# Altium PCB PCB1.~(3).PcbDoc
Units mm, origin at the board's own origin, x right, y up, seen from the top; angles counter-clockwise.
Board outline 70 x 70 mm, 4 copper layers (Top Layer, Internal Plane 1, Internal Plane 2, Bottom Layer), stack 0.462 mm thick; 10 components, 13 nets, 53 pads, 0 vias.
Unrouted connection lines stored in the file: 9.
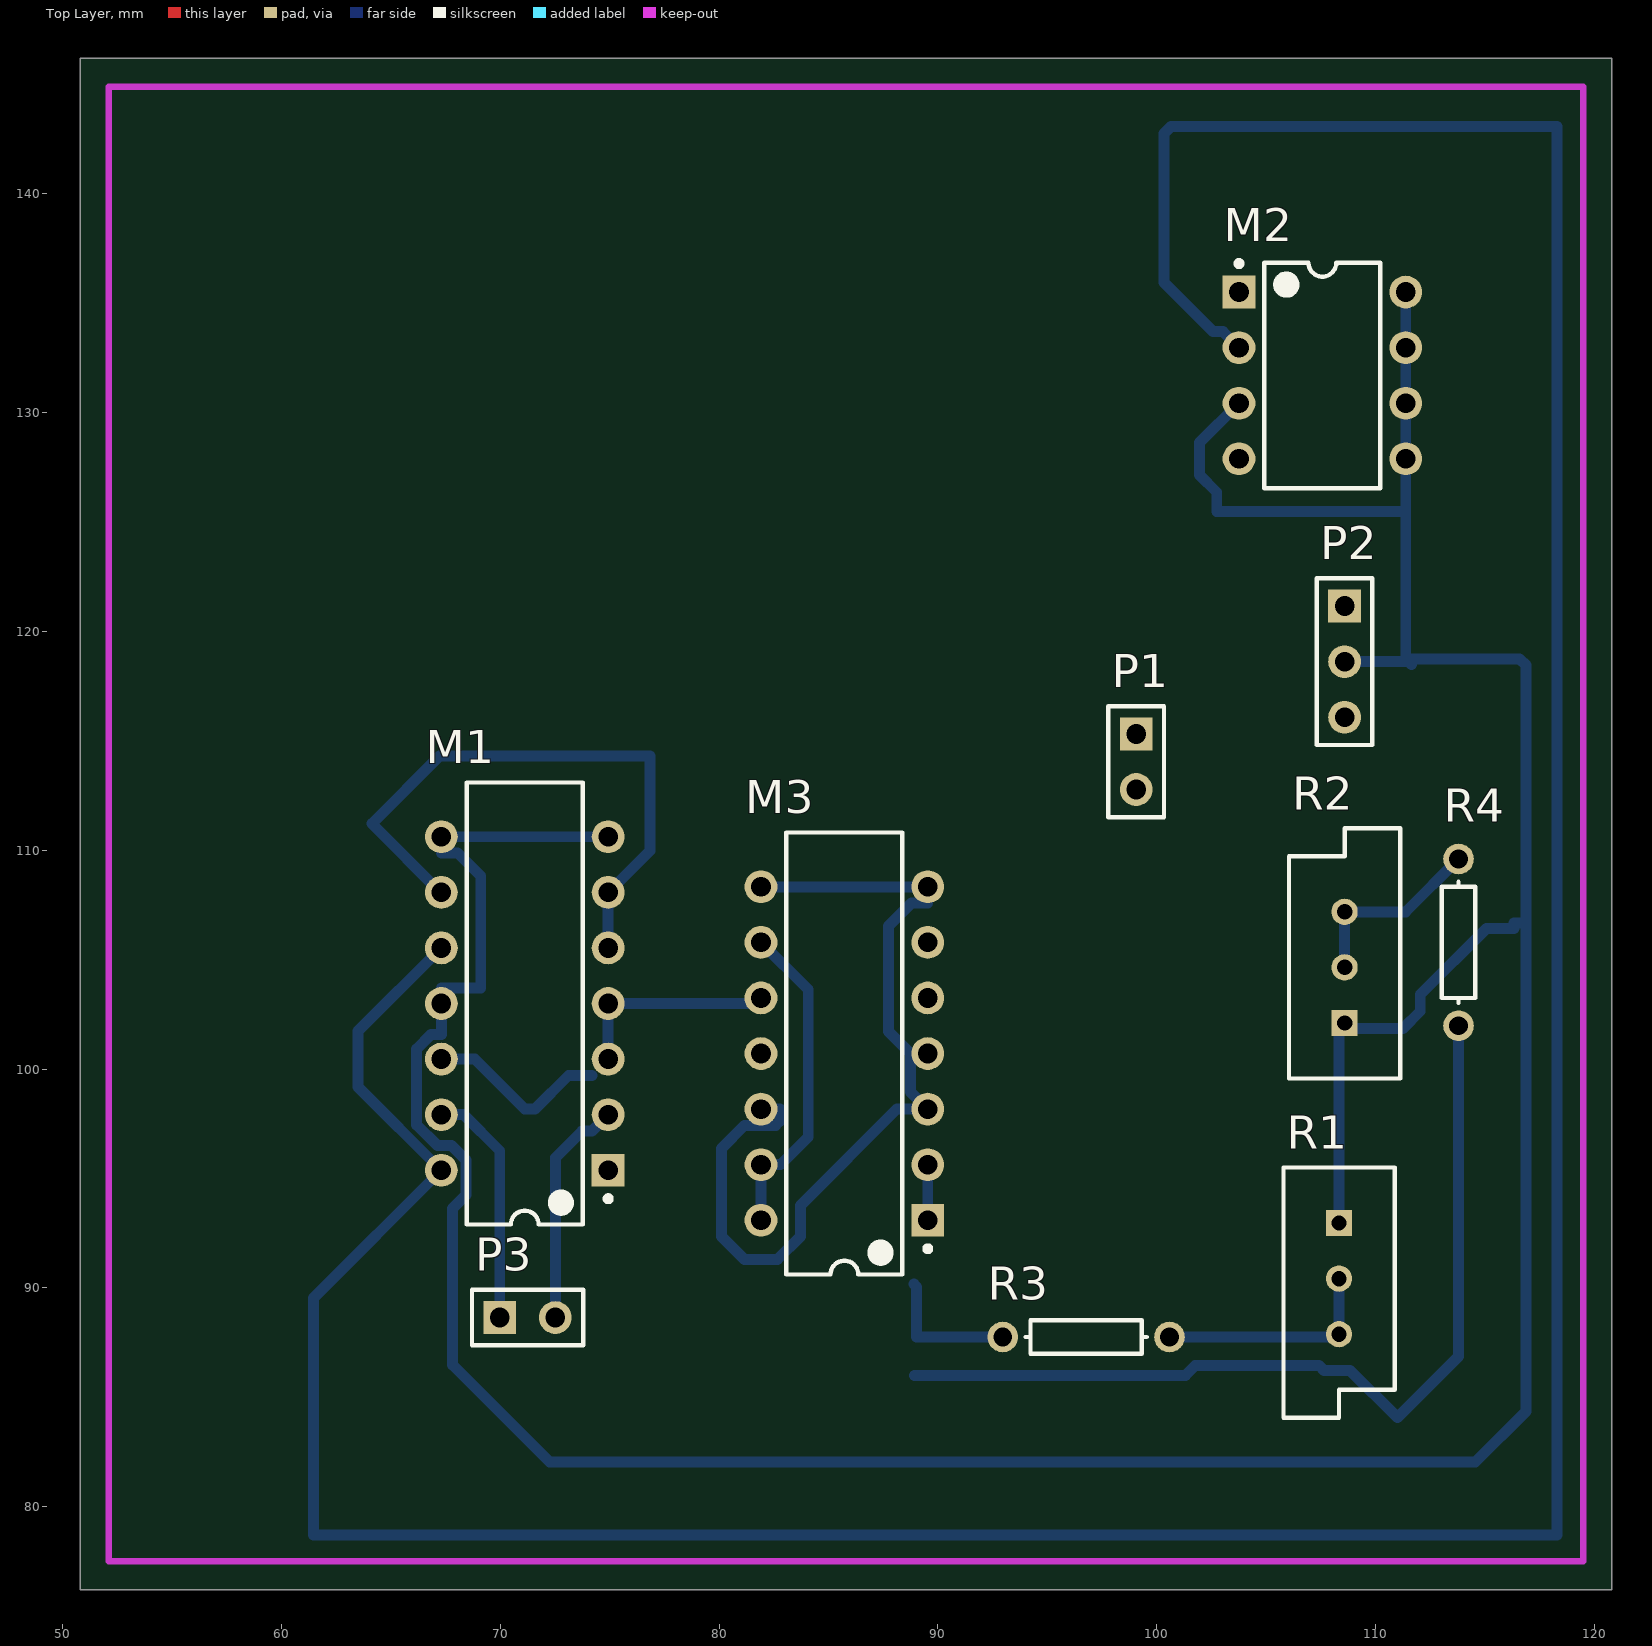
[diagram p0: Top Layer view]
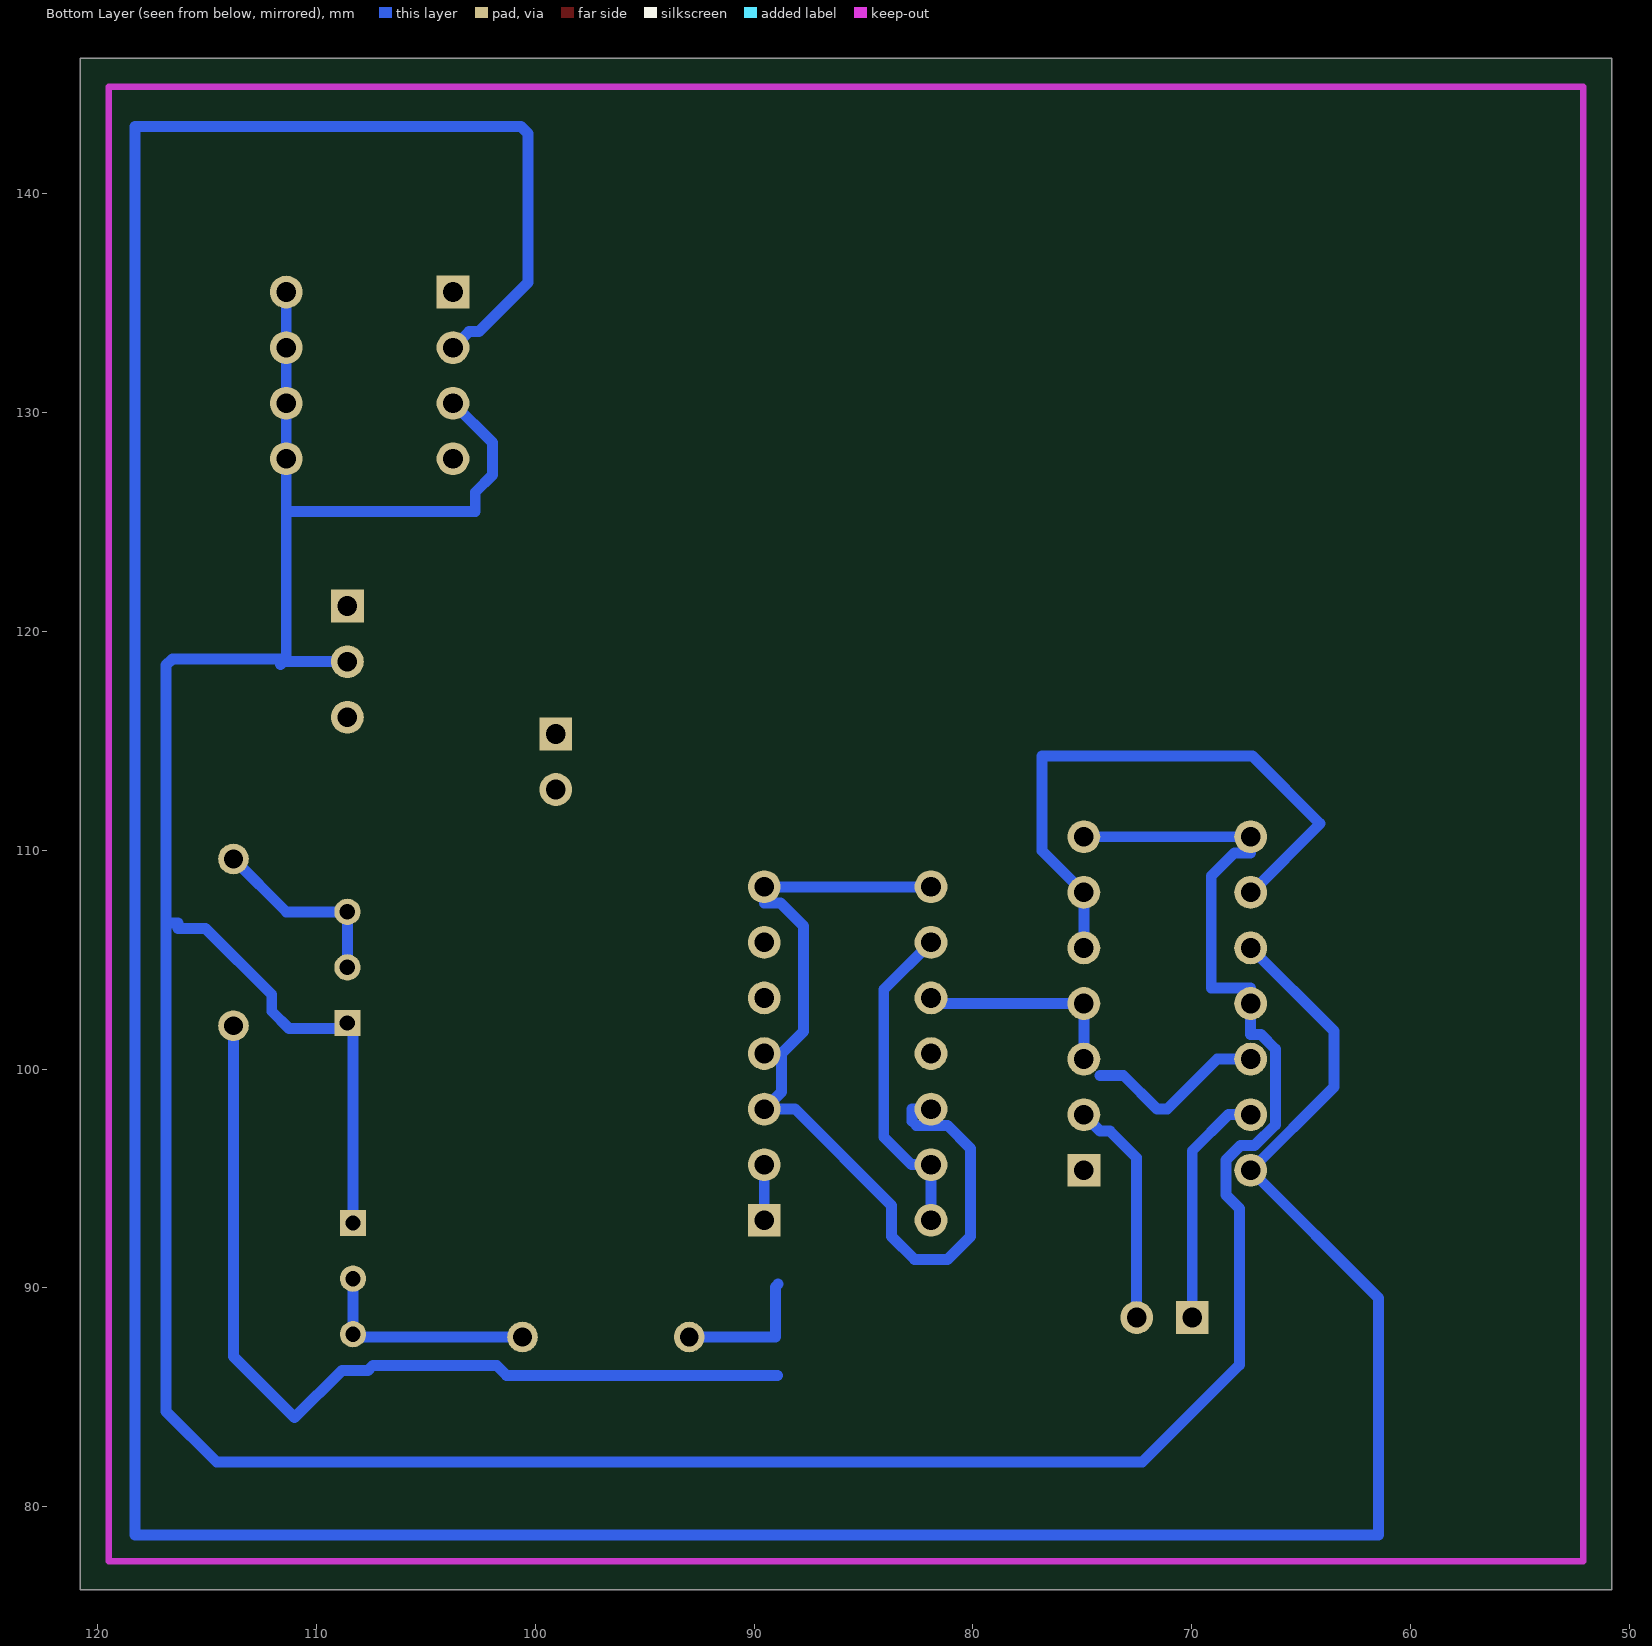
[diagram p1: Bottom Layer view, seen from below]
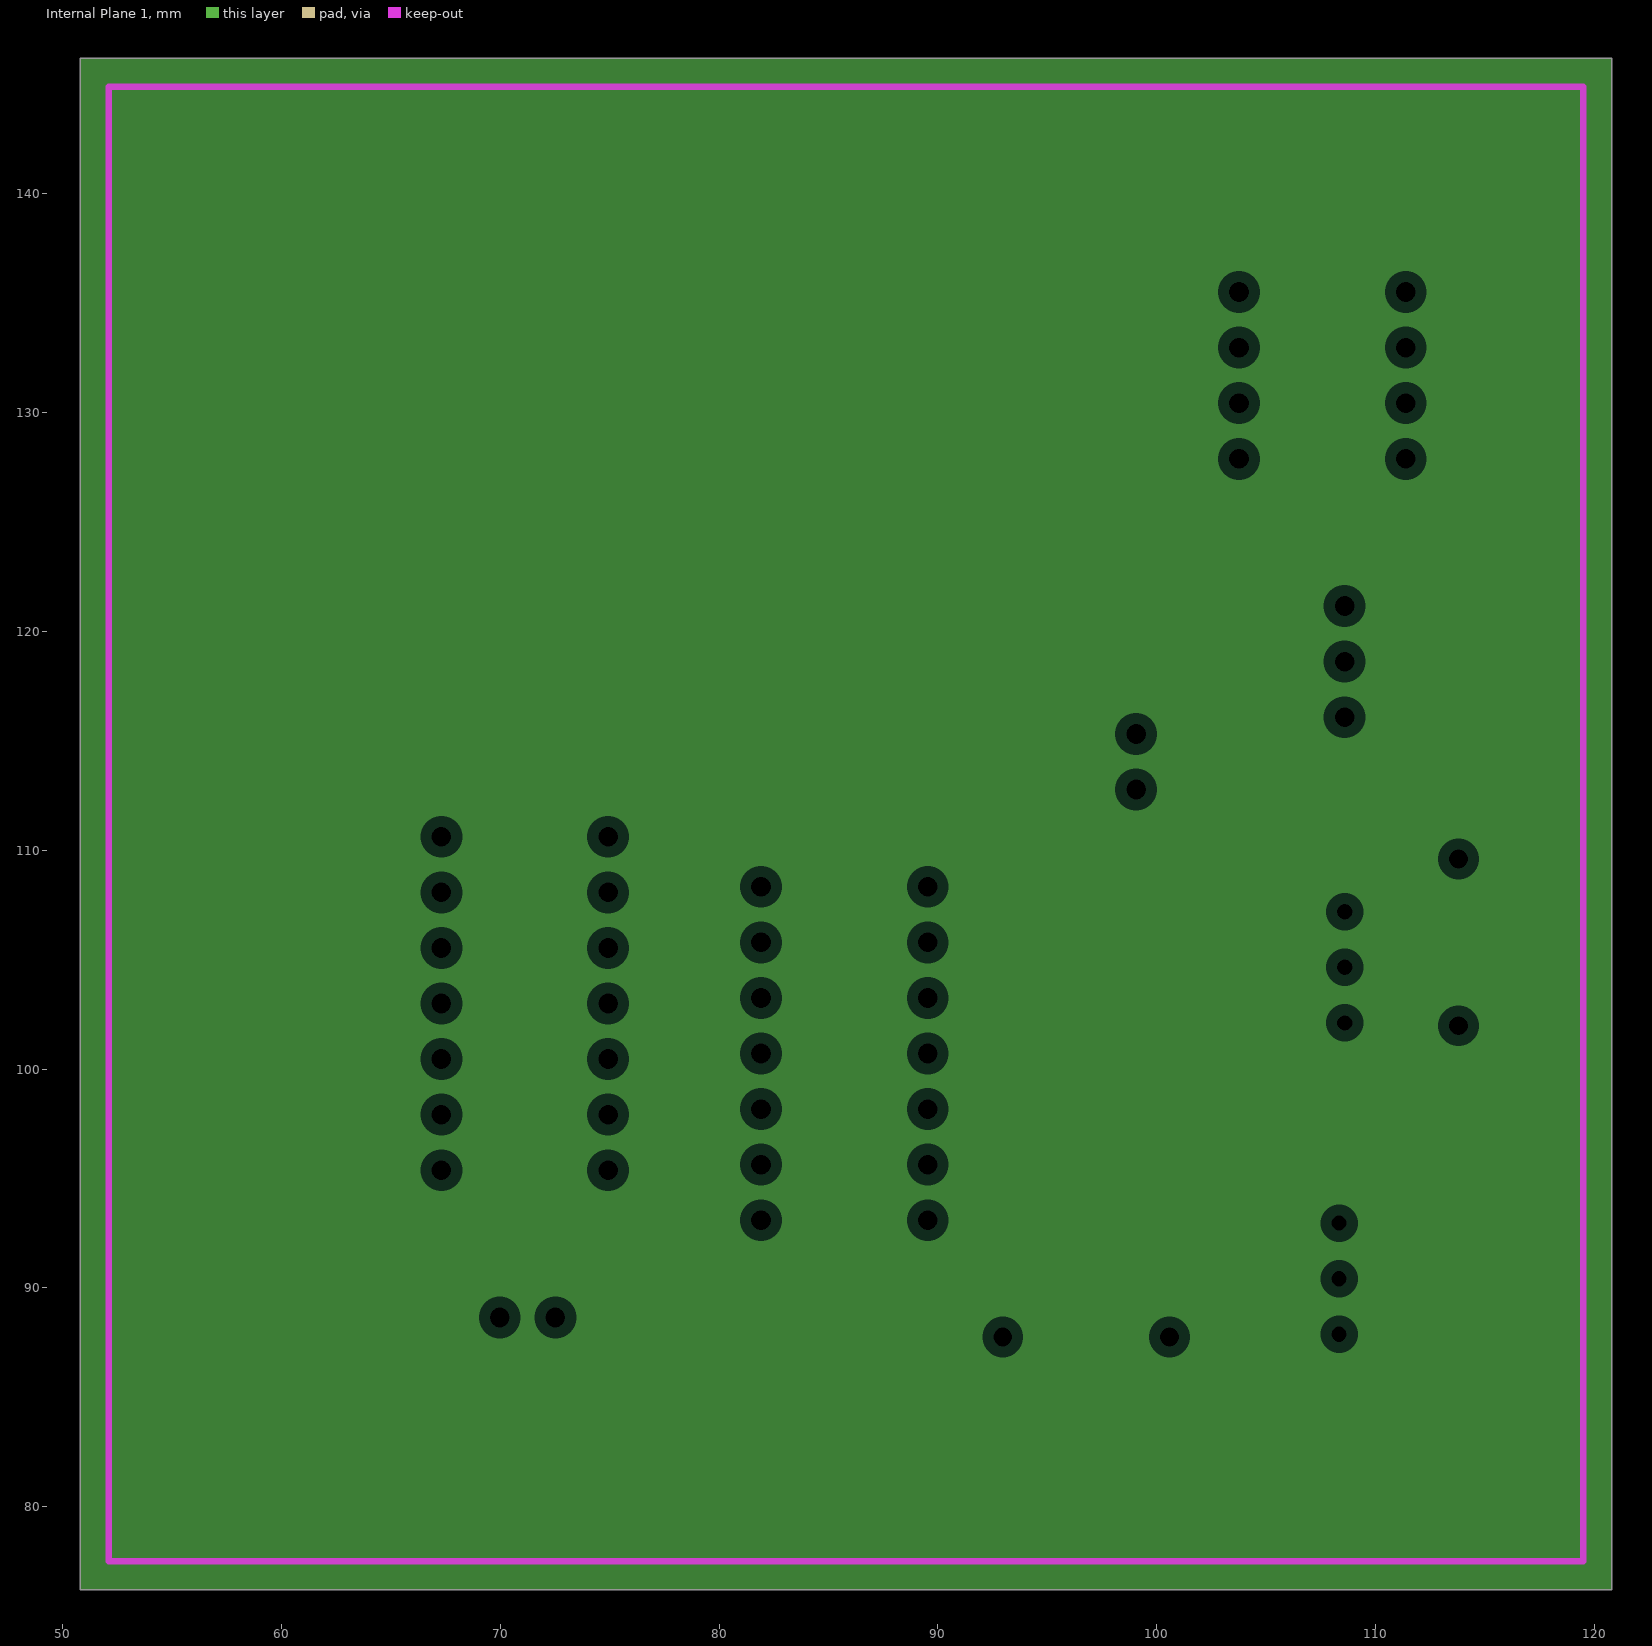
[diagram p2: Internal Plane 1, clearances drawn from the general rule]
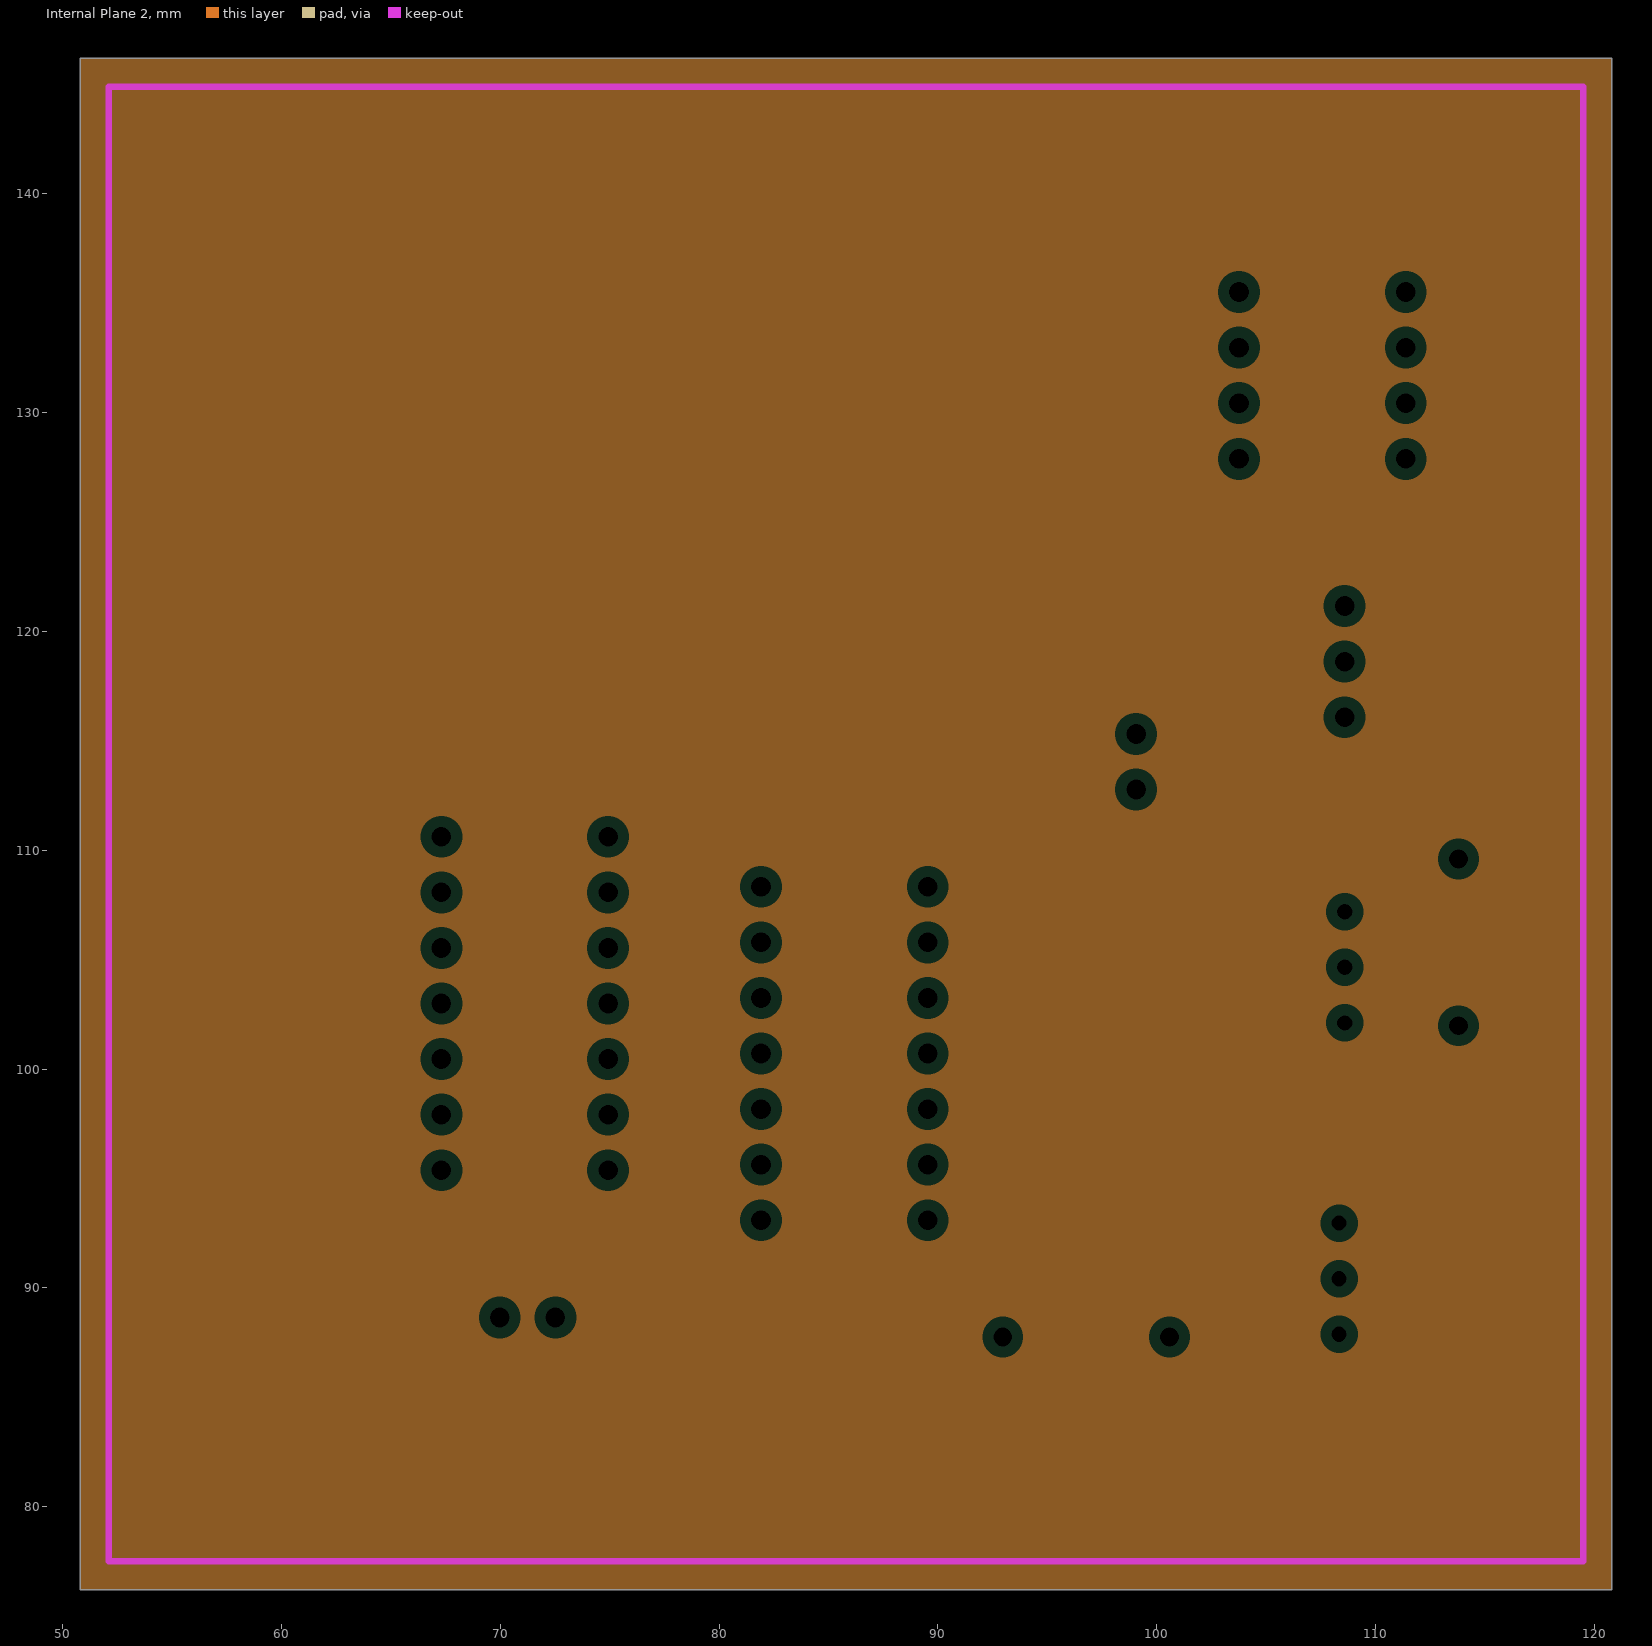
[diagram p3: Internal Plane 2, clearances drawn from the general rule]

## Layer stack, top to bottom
Top Solder: solder mask 0.0102, Solder Resist, Dk 3.5
Top Layer: signal copper 0.0356
Internal Plane 1: plane copper 0.0356
Internal Plane 2: plane copper 0.0356
Dielectric 1: dielectric 0.32, FR-4, Dk 4.8
Bottom Layer: signal copper 0.0356
Bottom Solder: solder mask 0.0102, Solder Resist, Dk 3.5

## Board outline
50.8,76.2 120.8,76.2 120.8,146.2 50.8,146.2

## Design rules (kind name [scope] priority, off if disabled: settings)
Clearance Clearance_1 [InNet('VDD')] p1: gap=0.127
Clearance [All] p2: gap=0.8
PlaneClearance [All] p1: clearance=0.508
PlaneConnect [All] p1: planeconnectstyle=Relief reliefexpansion=0.508 reliefentries=4 reliefconductorwidth=0.254 reliefairgap=0.254
PolygonConnect [All] p1: connectstyle=Relief reliefconductorwidth=0.254 reliefentries=4 polygonreliefangle="90 Angle" airgapwidth=0.254
RoutingVias [All] p1: holewidth=0.8 width=1.6 viastyle="Through Hole" minholewidth=0.711 minwidth=1.27 maxholewidth=0.711 maxwidth=1.27
SolderMaskExpansion [All] p1: expansion=0.102
Width [All] p1: maxlimit=0.5 minlimit=0.203 preferedwidth=0.5 toplayer_minwidth=0.5 minimp=50.000000 maximp=50.000000 favimp=50.000000
28 further rules are at their usual default settings.

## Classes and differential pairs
component class Sheet2: M2 M3 P1 P2 P3 R1 R2 R3 R4

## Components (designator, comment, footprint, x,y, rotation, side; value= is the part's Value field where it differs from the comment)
M1 "ALD1105" DIP-14 71.12,102.997 r180 top
M2 "ALD1117" DIP-8 107.569,131.699 r0 top
M3 "ALD1106" DIP-14 85.725,100.711 r180 top
P1 "Header 2" HDR1X2 99.06,115.316 r270 top
P2 "Header 3" HDR1X3 108.585,121.158 r270 top
P3 "Header 2" HDR1X2 69.977,88.646 r0 top
R1 "RPot" VR5 108.331,90.424 r270 top
R2 "RPot" VR5 108.585,104.648 r90 top
R3 "Res1" AXIAL-0.3 96.774,87.757 r180 top
R4 "Res1" AXIAL-0.3 113.792,105.791 r270 top

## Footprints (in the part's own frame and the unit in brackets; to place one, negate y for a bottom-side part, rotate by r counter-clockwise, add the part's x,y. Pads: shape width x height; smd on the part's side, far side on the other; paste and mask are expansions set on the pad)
AXIAL-0.3 [mm] "Axial Device, Thru-Hole; 2 Leads; 0.3 in Pin Spacing"
  round 1.4 hole 0.85: 1(-3.81,0) 2(3.81,0)
  silkscreen extent -2.77,-0.76 2.77,0.76
DIP-8 [mm] "DIP, 8-Pin, Row Spacing 7.62 mm, Pitch 2.54 mm"
  rect 1.5x1.5 hole 0.9: 1(-3.81,3.81)
  round 1.5 hole 0.9: 2(-3.81,1.27) 3(-3.81,-1.27) 4(-3.81,-3.81) 5(3.81,-3.81) 6(3.81,-1.27) 7(3.81,1.27) 8(3.81,3.81)
  silkscreen extent -3.93,-5.15 2.65,5.23, body extent -3.6,-5.15 3.6,5.15, height 5.33
DIP-14 [mm] "DIP, 14-Pin, Row Spacing 7.62 mm, Pitch 2.54 mm"
  rect 1.5x1.5 hole 0.9: 1(-3.81,7.62)
  round 1.5 hole 0.9: 2(-3.81,5.08) 3(-3.81,2.54) 4(-3.81,0) 5(-3.81,-2.54) 6(-3.81,-5.08) 7(-3.81,-7.62) 8(3.81,-7.62) 9(3.81,-5.08) 10(3.81,-2.54) 11(3.81,0) 12(3.81,2.54) 13(3.81,5.08) 14(3.81,7.62)
  silkscreen extent -3.94,-10.1 2.65,10.1, body extent -3.6,-10.1 3.6,10.1, height 5.08
HDR1X2 [mm] "Connector; Header; 2 Position"
  rect 1.5x1.5 hole 0.9: 1(0,0)
  round 1.5 hole 0.9: 2(2.54,0)
  silkscreen extent -1.27,-1.27 3.81,1.27
HDR1X3 [mm] "Connector; Header; 3 Position"
  rect 1.5x1.5 hole 0.9: 1(0,0)
  round 1.5 hole 0.9: 2(2.54,0) 3(5.08,0)
  silkscreen extent -1.27,-1.27 6.35,1.27
VR5 [mm] "Thru-Hole; 3 Leads"
  rect 1.2x1.2 hole 0.7: 1(-2.54,0)
  round 1.2 hole 0.7: 2(0,0) 3(2.54,0)
  silkscreen extent -5.08,-2.54 6.35,2.54

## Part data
M1: "Dual P-channel and dual N-channel matched MOSFET array"
M2: "Dual P-channel matched MOSFET array"
M3: "Quad N-channel matched MOSFET array"
P1 P3: "Header, 2-Pin"
P2: "Header, 3-Pin"
R1 R2: "Potentiometer"
R3 R4: "Resistor"

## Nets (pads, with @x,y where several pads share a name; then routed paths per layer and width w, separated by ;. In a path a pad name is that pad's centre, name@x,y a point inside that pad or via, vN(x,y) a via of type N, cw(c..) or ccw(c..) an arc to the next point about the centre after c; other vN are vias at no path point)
GND: P1.2 P2.3
IN+: M1.13 P3.1 | length 11
  Bottom Layer w0.5: M1.13 68.326,97.917 69.977,96.266 P3.1
IN-: M1.2 P3.2 | length 10.5
  Bottom Layer w0.5: P3.2 72.517,95.949 73.745,97.177 74.19,97.177 M1.2
NetM1_1: M1.1 M1.5 M1.6 M1.9 | length 28
  Bottom Layer w0.5: M1.9 67.272,108.077 64.135,111.214 67.221,114.3 76.835,114.3 76.835,109.976 74.936,108.077 M1.6 M1.5 M1.5@74.936,105.537
NetM1_3: M1.3 M1.4 M1.12 M3.10 | length 18.1
  Bottom Layer w0.5: M1.12 68.834,100.457 71.12,98.171 71.584,98.171 73.13,99.717 74.19,99.717 ; M1.3@74.936,100.457 M1.3 M1.4 81.661,102.997 M3.10
NetM1_10: M1.10 M1.14 M2.2 | length 183.2
  Bottom Layer w0.5: M1.10 67.304,105.537 63.5,101.733 63.5,99.181 67.304,95.377 61.468,89.541 61.468,78.7 118.3,78.7 118.3,143.066 100.648,143.066 100.33,142.748 100.33,135.953 102.574,133.709 103.019,133.709 M2.2
NetM3_1: M3.1 M3.2 M3.6 R3.2 | length 8.9
  Bottom Layer w0.5: 88.9,90.17 89.027,90.043 89.027,87.757 R3.2 ; M3.1 M3.2
NetM3_9: M3.9 M3.13 M3.14 R4.2 | length 57.3
  Bottom Layer w0.5: M3.14 M3.13 82.804,95.631 84.074,96.901 84.074,103.638 81.921,105.791 M3.9 ; 88.939,86.007 101.309,86.007 101.759,86.457 107.425,86.457 107.648,86.234 108.838,86.234 110.998,84.074 113.792,86.868 R4.2
NetR1_2: R1.2 R1.3 R3.1 | length 10.3
  Bottom Layer w0.5: R3.1 108.204,87.757 R1.3 R1.2
NetR2_2: R2.2 R2.3 R4.1 | length 8.7
  Bottom Layer w0.5: R2.2 R2.3 111.379,107.188 R4.1
OUT2: M2.1 M3.5 P1.1
VDD: M1.7 M1.8 M1.11 M2.3 M2.5 M2.6 M2.7 M2.8 P2.2 R1.1 R2.1 | length 182.2
  Bottom Layer w0.5: M1.11 67.31,101.584 66.843,101.584 66.183,100.924 66.183,97.45 67.129,96.504 67.777,96.504 68.437,95.844 68.437,94.25 67.818,93.631 67.818,86.487 72.263,82.042 114.554,82.042 116.873,84.361 116.873,106.68 ; M1.11@67.31,103.704 69.11,103.704 69.11,108.823 68.056,109.877 67.31,109.877 M1.8 M1.7 ; M2.3 103.753,130.429 101.959,128.635 101.959,127.143 102.743,126.359 102.743,125.476 111.379,125.476 ; R1.1 108.331,101.854 111.252,101.854 112.042,102.644 112.042,103.406 115.062,106.426 116.332,106.426 ; P2.2 111.506,118.618 111.633,118.491 ; M2.8 M2.7 M2.6 M2.5 111.379,125.476 ; 116.332,106.68 116.873,106.68 ; 111.379,125.476 111.379,118.745 116.586,118.745 116.873,118.458 116.873,106.68
VSS: M3.3 M3.4 M3.7 M3.8 M3.12 P2.1 | length 41.9
  Bottom Layer w0.5: M3.12 82.774,98.171 82.774,97.616 82.589,97.431 81.169,97.431 80.115,96.377 80.115,92.345 81.169,91.291 82.661,91.291 83.715,92.345 83.715,93.765 88.121,98.171 M3.3 88.748,98.958 88.748,100.711 87.735,101.724 87.735,106.537 88.789,107.591 89.535,107.591 M3.7 M3.8
pads on no net: M2.4 M3.11

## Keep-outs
Keep-Out Layer:
  lines w0.3: 52.1,77.5 52.1,144.9 119.5,144.9 119.5,77.5 52.1,77.5

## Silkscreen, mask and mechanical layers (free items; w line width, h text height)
Drill Drawing:
  text ".LEGEND" at 125.88,81.28 h1.52
  text "Drill Drawing." at 125.88,78.74 h1.52

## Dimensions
52.1,77.5 to 52.1,144.9 on Mechanical 1
52.1,77.5 to 119.5,77.5 on Mechanical 1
